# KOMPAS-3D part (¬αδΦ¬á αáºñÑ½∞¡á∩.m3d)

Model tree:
1. Эскиз:1
2. Операция выдавливания:1
     Расстояние 1 = 2
3. Эскиз:2
4. Операция выдавливания:2
     Расстояние 1 = 3
5. Эскиз:4
6. Вырезать элемент выдавливания:2
     Расстояние 1 = 5
